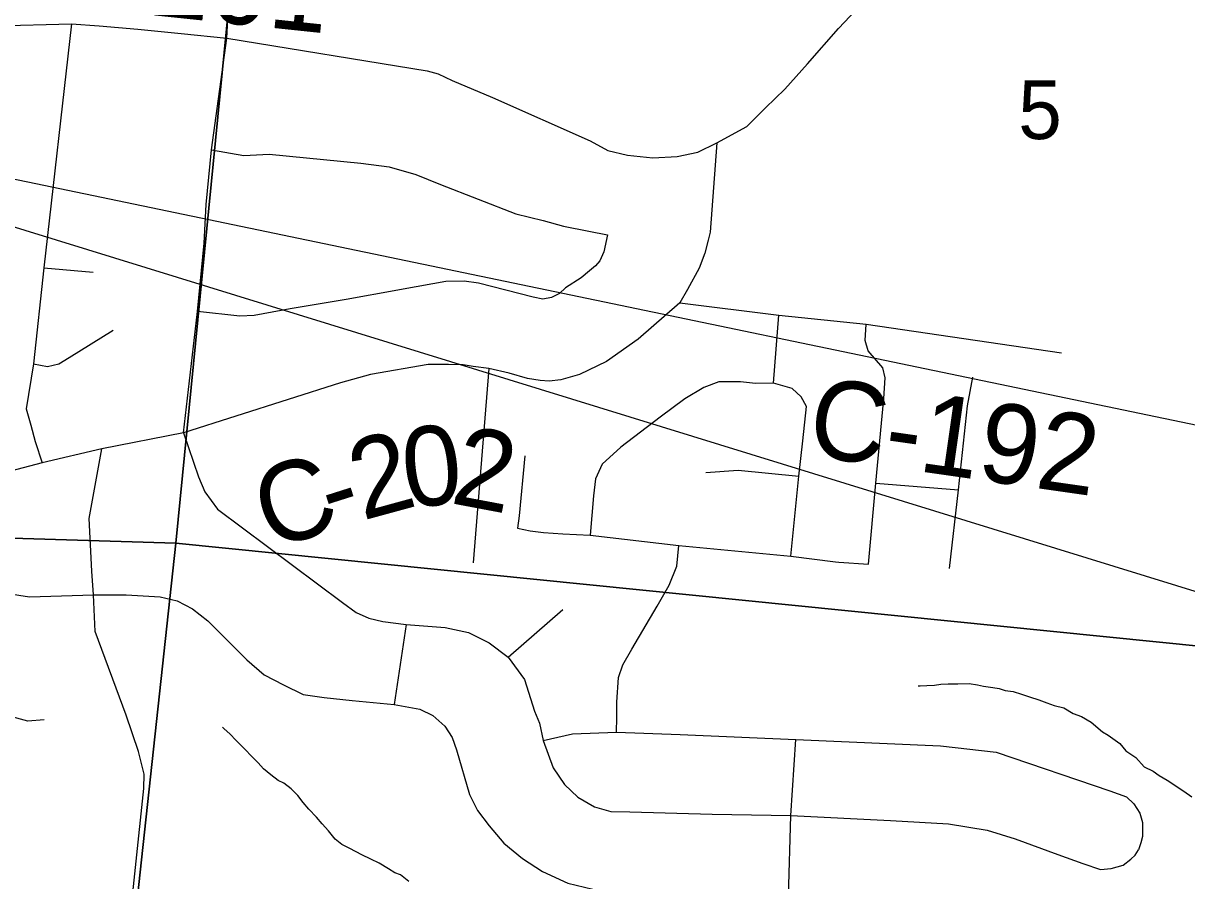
# Model space of a CAD drawing. Extents: x 0 to 34, y -2 to 22.
# Drawn here: x 5.919 to 6.75, y 15.439 to 16.052 of the extents above; entities that cross this region are included whole.
import ezdxf

# ---------------------------------------------------------------- set-up
doc = ezdxf.new("R2010")
doc.units = 0
for name, color, linetype in [('GM_X_County_Road', 7, 'Continuous'), ('GM_X_County_Road_Text', 7, 'Continuous'), ('GM_X_Minor_River', 7, 'Continuous'), ('GM_X_Section', 7, 'Continuous'), ('GM_X_Section_Text', 7, 'Continuous'), ('GM_X_Township_Road', 7, 'Continuous'), ('SH_Data', 7, 'Continuous')]:
    doc.layers.add(name, color=color, linetype=linetype)

msp = doc.modelspace()

# ---------------------------------------------------------------- linework, layer by layer
at = {"layer": 'GM_X_County_Road'}
msp.add_line((6.03353, 15.75896), (5.97524, 15.7477), dxfattribs=at)
for points in [[(6.03353, 15.75896), (6.04342, 15.84582), (6.04838, 15.89453), (6.04974, 15.92212), (6.05351, 15.96129), (6.06458, 16.04099), (6.0702, 16.14953), (6.07625, 16.20883), (6.10076, 16.44917), (6.10818, 16.52173), (6.11491, 16.57541), (6.13156, 16.70451)], [(5.89873, 16.04989), (5.95349, 16.05126), (5.97331, 16.04989), (6.00083, 16.04741), (6.03191, 16.04426), (6.06458, 16.04099), (6.20754, 16.0177), (6.21543, 16.01559), (6.22552, 16.01078), (6.25436, 15.99864), (6.32396, 15.9676), (6.33664, 15.96082), (6.35056, 15.95741), (6.36869, 15.95542), (6.38614, 15.95648), (6.40098, 15.9595), (6.41441, 15.96635), (6.43593, 15.97792), (6.44916, 15.99122), (6.46315, 16.00451), (6.47915, 16.02267), (6.50141, 16.04787), (6.53416, 16.08304)], [(6.41441, 15.96635), (6.40968, 15.90238), (6.40839, 15.89673), (6.40587, 15.88731), (6.4018, 15.8768), (6.39344, 15.86147), (6.38799, 15.85187), (6.35841, 15.82599), (6.33564, 15.8099), (6.3163, 15.80061), (6.30303, 15.79693), (6.29465, 15.79591), (6.28832, 15.79632), (6.27933, 15.79796), (6.26606, 15.80163), (6.25156, 15.8049), (6.24033, 15.80653), (6.23338, 15.80755), (6.22277, 15.80776), (6.20826, 15.80776), (6.16721, 15.80061), (6.14577, 15.79469), (6.03353, 15.75896)], [(6.38799, 15.85187), (6.45885, 15.84309), (6.52115, 15.83656), (6.66069, 15.81612)], [(5.97524, 15.7477), (5.93258, 15.73752), (5.85281, 15.71676)], [(5.95409, 15.18833), (5.9561, 15.18833), (5.96424, 15.1883), (5.97384, 15.23582), (5.98531, 15.31097), (5.98902, 15.3507), (5.99386, 15.3966), (6.00527, 15.50498), (6.00553, 15.51522), (6.00142, 15.53125), (5.99265, 15.55727), (5.9704, 15.61702), (5.96918, 15.64333), (5.96815, 15.66031), (5.96612, 15.69791), (5.97524, 15.7477)]]:
    msp.add_lwpolyline(points, dxfattribs=at)
at = {"layer": 'GM_X_Minor_River'}
for points in [[(6.55822, 15.57818), (6.55963, 15.57825), (6.56459, 15.5785), (6.56992, 15.57873), (6.5745, 15.57936), (6.57983, 15.5796), (6.58668, 15.57979), (6.59467, 15.57995), (6.60073, 15.57902), (6.60489, 15.57814), (6.61171, 15.57719), (6.61625, 15.5763), (6.6204, 15.57504), (6.62607, 15.57412), (6.63211, 15.57243), (6.63776, 15.57037), (6.64455, 15.56827), (6.6502, 15.56621), (6.65547, 15.56416), (6.66227, 15.56245), (6.669, 15.55846), (6.67503, 15.55638), (6.68177, 15.55239), (6.68994, 15.54531), (6.69406, 15.54291), (6.70227, 15.53697), (6.70669, 15.53189), (6.71379, 15.52712), (6.71969, 15.52049), (6.72607, 15.51727), (6.73055, 15.51409), (6.73617, 15.51089), (6.74812, 15.50294), (6.75372, 15.49898)], [(6.19457, 15.43838), (6.18861, 15.44312), (6.18448, 15.44476), (6.17999, 15.44755), (6.17325, 15.45154), (6.16724, 15.45437), (6.16086, 15.4576), (6.15224, 15.46203), (6.14661, 15.46485), (6.14177, 15.46879), (6.13699, 15.47464), (6.13256, 15.47971), (6.12851, 15.4844), (6.12296, 15.49026), (6.1189, 15.49495), (6.11524, 15.5), (6.11042, 15.5047), (6.1052, 15.50865), (6.10108, 15.51067), (6.09586, 15.51463), (6.09065, 15.51896), (6.08697, 15.52325), (6.08178, 15.52835), (6.07771, 15.53265), (6.07105, 15.53931), (6.06661, 15.544), (6.06252, 15.54755), (6.06131, 15.54883)]]:
    msp.add_lwpolyline(points, dxfattribs=at)
at = {"layer": 'GM_X_Section'}
for points in [[(6.12883, 16.70302), (6.02813, 15.68024), (5.03632, 15.71052), (5.14268, 16.73204)], [(7.1499, 16.57812), (7.05954, 15.57632), (6.02813, 15.68024), (6.12883, 16.70302)]]:
    msp.add_lwpolyline(points, close=True, dxfattribs=at)
for points in [[(4.95495, 14.72063), (5.03632, 15.71052), (6.02813, 15.68024), (5.92588, 14.73781), (5.92389, 14.73368)], [(5.92588, 14.73781), (6.02813, 15.68024), (7.05954, 15.57632)]]:
    msp.add_lwpolyline(points, dxfattribs=at)
at = {"layer": 'GM_X_Township_Road'}
for p, q in [((5.93368, 15.87692), (5.96905, 15.87375)), ((6.45498, 15.79449), (6.45885, 15.84309)), ((6.25156, 15.8049), (6.24033, 15.66623)), ((6.52799, 15.7231), (6.58722, 15.71831)), ((6.26535, 15.59883), (6.30456, 15.63273)), ((6.19264, 15.62211), (6.18406, 15.56493))]:
    msp.add_line(p, q, dxfattribs=at)
for points in [[(5.95349, 16.05126), (5.93368, 15.87692), (5.92639, 15.80825), (5.92126, 15.77609), (5.9246, 15.76449), (5.92763, 15.75293), (5.93258, 15.73752)], [(6.05351, 15.96129), (6.07658, 15.95709), (6.09468, 15.95824), (6.16018, 15.95164), (6.18054, 15.94916), (6.19953, 15.94365), (6.21715, 15.9365), (6.27082, 15.91558), (6.29035, 15.91077), (6.30494, 15.90677), (6.3231, 15.9032), (6.33631, 15.90045)], [(6.33631, 15.90045), (6.3337, 15.88847), (6.33081, 15.88201), (6.32778, 15.87829), (6.32351, 15.87472), (6.3176, 15.86989), (6.30645, 15.86261), (6.30205, 15.85862), (6.29641, 15.85573), (6.29021, 15.85448), (6.2832, 15.85586), (6.24426, 15.86591), (6.23401, 15.86742), (6.22093, 15.86728), (6.19052, 15.86178), (6.18672, 15.86109)], [(6.18672, 15.86109), (6.14965, 15.85435), (6.10974, 15.84761), (6.08401, 15.84279), (6.07383, 15.84237), (6.04342, 15.84582)], [(5.92639, 15.80825), (5.9363, 15.80632), (5.94442, 15.80825), (5.95185, 15.81293), (5.98322, 15.83247)], [(6.52278, 15.6651), (6.52799, 15.7231), (6.53381, 15.78346), (6.53483, 15.79836), (6.53299, 15.80551), (6.52258, 15.81756), (6.52053, 15.82512), (6.52115, 15.83656)], [(6.58058, 15.66204), (6.58722, 15.71831), (6.59344, 15.77825), (6.59733, 15.79887)], [(6.46744, 15.67103), (6.47295, 15.72811), (6.47601, 15.75323), (6.47847, 15.77794), (6.47479, 15.78468), (6.46825, 15.79081), (6.45498, 15.79449), (6.44211, 15.79428), (6.43128, 15.7955), (6.41597, 15.7955), (6.40514, 15.79142), (6.39167, 15.78325), (6.3741, 15.77018), (6.34591, 15.74873), (6.33264, 15.73669), (6.32774, 15.72627), (6.32631, 15.71402), (6.32406, 15.68583)], [(6.03353, 15.75896), (6.04416, 15.72771), (6.04879, 15.71697), (6.05793, 15.70459), (6.14709, 15.63784), (6.1569, 15.63069), (6.16589, 15.6266), (6.17589, 15.62416), (6.19264, 15.62211), (6.22042, 15.62007), (6.23716, 15.61639), (6.25186, 15.60904), (6.26535, 15.59883), (6.27719, 15.5829), (6.28429, 15.5602), (6.28782, 15.5516), (6.29047, 15.53928), (6.29762, 15.51958), (6.30579, 15.50774), (6.31518, 15.49876), (6.32702, 15.49181), (6.33887, 15.48854), (6.35235, 15.48814), (6.41116, 15.4865), (6.46723, 15.48568)], [(6.27729, 15.74261), (6.27321, 15.69972), (6.27219, 15.69094), (6.28117, 15.6891), (6.29077, 15.68788), (6.30446, 15.68685), (6.32406, 15.68583), (6.38727, 15.67848), (6.46744, 15.67103), (6.49916, 15.66685)], [(6.40657, 15.73076), (6.42965, 15.7324), (6.47295, 15.72811)], [(6.34275, 15.54512), (6.34316, 15.55553), (6.34316, 15.56656), (6.34418, 15.58413), (6.34745, 15.59332), (6.35369, 15.60436), (6.37196, 15.63518), (6.38033, 15.65009), (6.38584, 15.66377), (6.38727, 15.67848)], [(6.49916, 15.66685), (6.50154, 15.66653), (6.52278, 15.6651)], [(5.93396, 15.55396), (5.92239, 15.55313), (5.91442, 15.55506), (5.90589, 15.55726), (5.89873, 15.56304), (5.89643, 15.5704), (5.90369, 15.64505), (5.9235, 15.64175), (5.96918, 15.64333)], [(5.96918, 15.64333), (5.99258, 15.6434), (6.01679, 15.64175), (6.0289, 15.63899), (6.03991, 15.63321), (6.05092, 15.62468), (6.07872, 15.59689), (6.0911, 15.58616), (6.10486, 15.579), (6.11891, 15.57207), (6.13403, 15.57003), (6.15404, 15.56778), (6.18406, 15.56493)], [(6.18406, 15.56493), (6.20224, 15.56166), (6.21163, 15.55717), (6.22021, 15.5494), (6.22532, 15.54144), (6.22858, 15.53266), (6.23778, 15.5006), (6.24349, 15.48916), (6.25186, 15.47833), (6.26228, 15.46587), (6.27576, 15.45484), (6.29006, 15.44565), (6.30814, 15.43728), (6.3258, 15.43289), (6.35531, 15.43105), (6.41127, 15.42901), (6.4656, 15.42758), (6.52676, 15.42594), (6.54188, 15.42145), (6.56108, 15.41247), (6.577, 15.40471), (6.58497, 15.39777), (6.59008, 15.39286)], [(6.29047, 15.53928), (6.3113, 15.54389), (6.34275, 15.54512), (6.38829, 15.54348), (6.4708, 15.54001), (6.57414, 15.53552), (6.61407, 15.53092), (6.69516, 15.50335), (6.707, 15.49906), (6.71241, 15.49397), (6.7166, 15.48722), (6.71864, 15.48068), (6.71864, 15.47537), (6.71864, 15.47067), (6.71741, 15.46618), (6.71578, 15.46108)], [(6.59008, 15.39286), (6.58068, 15.38571), (6.57271, 15.37836), (6.56434, 15.37019), (6.55229, 15.36018), (6.51747, 15.32587), (6.50848, 15.31627), (6.49756, 15.33037), (6.47315, 15.38531), (6.46845, 15.39858), (6.46601, 15.41288), (6.4656, 15.42758), (6.46723, 15.48568), (6.4708, 15.54001)], [(6.46723, 15.48568), (6.53861, 15.48201), (6.57987, 15.47956), (6.60764, 15.47506), (6.62755, 15.46884), (6.65818, 15.45781), (6.67596, 15.45127), (6.68862, 15.44698), (6.69617, 15.4478), (6.70475, 15.45025), (6.71027, 15.45454), (6.71333, 15.4574), (6.71578, 15.46108)]]:
    msp.add_lwpolyline(points, dxfattribs=at)
at = {"layer": 'SH_Data'}
msp.add_lwpolyline([(5.57425, 16.01053), (9.9214, 14.66899), (9.92472, 15.10505)], close=True, dxfattribs=at)

# ---------------------------------------------------------------- texts
at = {"layer": 'GM_X_County_Road_Text'}
for s, height, rotation, p in [('C-201', 0.056818, 353.98403, (5.92903, 16.0661)), ('C-192', 0.056818, 351.86961, (6.47791, 15.74313)), ('0', 0.05682, 6.24666, (6.19277, 15.70502)), ('2', 0.05682, 15.27988, (6.16133, 15.69624)), ('2', 0.05682, 349.31953, (6.22314, 15.709)), ('C', 0.05682, 17.71568, (6.09525, 15.67515)), ('-', 0.05682, 17.62958, (6.13968, 15.68934))]:
    msp.add_text(s, height=height, rotation=rotation, dxfattribs=at).set_placement(p)
at = {"layer": 'GM_X_Section_Text'}
msp.add_text('5', height=0.04186, rotation=0.00001, dxfattribs=at).set_placement((6.62978, 15.96894))

doc.saveas('drawing.dxf')
